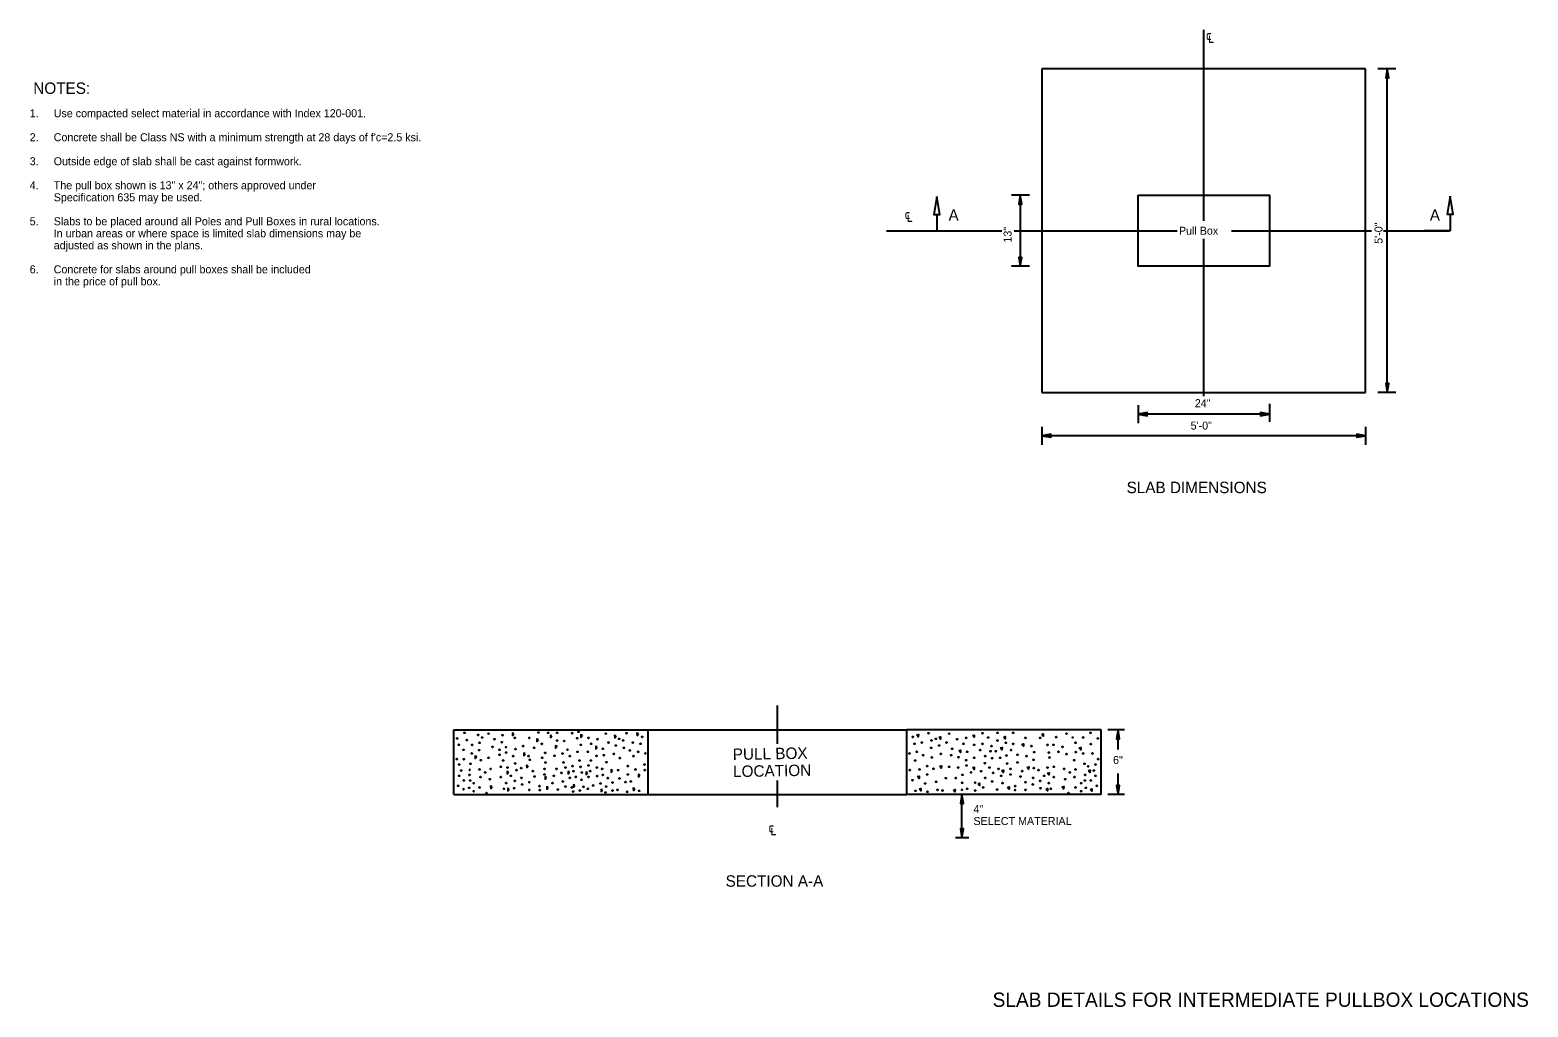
# Model space of a CAD drawing. Extents: x 10083 to 10738, y 10044 to 10472.
import ezdxf

# ---------------------------------------------------------------- set-up
doc = ezdxf.new("R2010")
doc.units = 0
doc.layers.add('Default', color=7, linetype='Continuous')
doc.layers.add('Dimension', color=7, linetype='Continuous')

msp = doc.modelspace()

# ---------------------------------------------------------------- linework, layer by layer
at = {"layer": 'Default'}
for p, q in [((10596.24, 10388), (10596.24, 10471.52)), ((10525.46, 10454.51), (10525.46, 10312.95)), ((10667.02, 10454.51), (10525.46, 10454.51)), ((10667.02, 10312.95), (10667.02, 10454.51)), ((10680.27, 10454.51), (10672.4, 10454.51)), ((10676.48, 10312.95), (10676.48, 10454.51)), ((10520.08, 10399.3), (10512.21, 10399.3)), ((10516, 10399.3), (10516, 10368.16)), ((10457.46, 10383.73), (10507.34, 10383.73)), ((10506.24, 10383.73), (10507.97, 10383.73)), ((10513.3, 10383.73), (10584.64, 10383.73)), ((10596.24, 10311.43), (10596.24, 10380.23)), ((10608.31, 10383.73), (10669.64, 10383.73)), ((10674.77, 10383.73), (10703.82, 10383.73)), ((10677.04, 10383.73), (10684.02, 10383.73)), ((10520.08, 10368.16), (10512.21, 10368.16)), ((10525.46, 10312.95), (10667.02, 10312.95)), ((10680.27, 10312.95), (10672.4, 10312.95)), ((10567.54, 10307.43), (10567.54, 10299.56)), ((10624.95, 10308), (10624.95, 10300.13)), ((10624.95, 10303.5), (10567.54, 10303.5)), ((10525.46, 10297.98), (10525.46, 10290.1)), ((10667.02, 10294.04), (10525.46, 10294.04)), ((10667.02, 10297.98), (10667.02, 10290.1)), ((10409.81, 10159.41), (10409.81, 10176.1)), ((10268.22, 10165.47), (10353.2, 10165.47)), ((10268.22, 10137.16), (10268.22, 10165.47)), ((10353.2, 10137.16), (10353.2, 10165.47)), ((10353.2, 10165.47), (10466.42, 10165.47)), ((10466.42, 10137.16), (10466.42, 10165.47)), ((10551.4, 10165.47), (10466.42, 10165.47)), ((10551.4, 10137.16), (10551.4, 10165.47)), ((10561.58, 10165.47), (10554.23, 10165.47)), ((10558.74, 10156.86), (10558.74, 10165.47)), ((10409.81, 10131.69), (10409.81, 10143.25)), ((10558.74, 10137.16), (10558.74, 10146.31)), ((10268.22, 10137.16), (10353.2, 10137.16)), ((10353.2, 10137.16), (10466.42, 10137.16)), ((10551.4, 10137.16), (10466.74, 10137.16)), ((10490.5, 10118.25), (10490.5, 10137.16)), ((10561.58, 10137.16), (10554.23, 10137.16)), ((10493.57, 10118.24), (10487.62, 10118.24))]:
    msp.add_line(p, q, dxfattribs=at)
msp.add_lwpolyline([(10567.54, 10399.3), (10624.95, 10399.3), (10624.95, 10368.16), (10567.54, 10368.16)], close=True, dxfattribs=at)
for points in [[(10294.57, 10163.83), (10293.91, 10164.03), (10293.97, 10163.02), (10294.57, 10163.83)], [(10305.25, 10161.21), (10304.59, 10161.42), (10304.64, 10160.41), (10305.25, 10161.21)], [(10311.16, 10162.84), (10310.5, 10163.04), (10310.56, 10162.04), (10311.16, 10162.84)], [(10324.5, 10163.07), (10323.84, 10163.28), (10323.89, 10162.27), (10324.5, 10163.07)], [(10339.27, 10162.83), (10338.61, 10163.03), (10338.66, 10162.02), (10339.27, 10162.83)], [(10349.03, 10163.85), (10348.37, 10164.05), (10348.42, 10163.04), (10349.03, 10163.85)], [(10470.77, 10163.28), (10471.43, 10163.48), (10471.37, 10162.47), (10470.77, 10163.28)], [(10480.47, 10162.25), (10481.13, 10162.46), (10481.08, 10161.45), (10480.47, 10162.25)], [(10495.2, 10162.99), (10495.86, 10163.19), (10495.8, 10162.19), (10495.2, 10162.99)], [(10508.79, 10162.32), (10509.45, 10162.53), (10509.39, 10161.52), (10508.79, 10162.32)], [(10525.4, 10163.47), (10526.06, 10163.67), (10526.01, 10162.66), (10525.4, 10163.47)], [(10299.55, 10155.04), (10298.89, 10155.25), (10298.95, 10154.24), (10299.55, 10155.04)], [(10313.41, 10158.2), (10312.75, 10158.41), (10312.81, 10157.4), (10313.41, 10158.2)], [(10331.03, 10158.01), (10330.37, 10158.21), (10330.43, 10157.21), (10331.03, 10158.01)], [(10489.24, 10156.37), (10489.9, 10156.57), (10489.84, 10155.57), (10489.24, 10156.37)], [(10507.35, 10157.58), (10508.01, 10157.78), (10507.95, 10156.78), (10507.35, 10157.58)], [(10516.75, 10159.1), (10517.41, 10159.3), (10517.36, 10158.3), (10516.75, 10159.1)], [(10541.82, 10157.52), (10542.48, 10157.72), (10542.42, 10156.72), (10541.82, 10157.52)], [(10275.47, 10148.04), (10275.14, 10148.15), (10275.17, 10147.64), (10275.47, 10148.04)], [(10278.29, 10153.68), (10277.63, 10153.88), (10277.68, 10152.88), (10278.29, 10153.68)], [(10300.78, 10149.73), (10300.12, 10149.93), (10300.18, 10148.92), (10300.78, 10149.73)], [(10337.68, 10147.82), (10337.02, 10148.02), (10337.08, 10147.01), (10337.68, 10147.82)], [(10480.85, 10149.54), (10481.51, 10149.74), (10481.45, 10148.74), (10480.85, 10149.54)], [(10495.23, 10148.94), (10495.89, 10149.14), (10495.84, 10148.14), (10495.23, 10148.94)], [(10519.04, 10149.02), (10519.7, 10149.22), (10519.65, 10148.22), (10519.04, 10149.02)], [(10292.19, 10146.97), (10291.54, 10147.18), (10291.59, 10146.17), (10292.19, 10146.97)], [(10308.87, 10144.72), (10308.21, 10144.92), (10308.27, 10143.91), (10308.87, 10144.72)], [(10318.92, 10147.05), (10318.26, 10147.25), (10318.31, 10146.24), (10318.92, 10147.05)], [(10321.23, 10141.25), (10320.58, 10141.45), (10320.63, 10140.45), (10321.23, 10141.25)], [(10326.8, 10146.74), (10326.14, 10146.94), (10326.19, 10145.93), (10326.8, 10146.74)], [(10349.68, 10145.68), (10349.02, 10145.88), (10349.08, 10144.87), (10349.68, 10145.68)], [(10471.11, 10145.03), (10471.77, 10145.24), (10471.71, 10144.23), (10471.11, 10145.03)], [(10497.57, 10141.87), (10498.23, 10142.08), (10498.18, 10141.07), (10497.57, 10141.87)], [(10507.97, 10147.64), (10508.63, 10147.84), (10508.58, 10146.84), (10507.97, 10147.64)], [(10527.93, 10146.52), (10528.59, 10146.72), (10528.53, 10145.72), (10527.93, 10146.52)], [(10545.85, 10147.67), (10546.51, 10147.88), (10546.46, 10146.87), (10545.85, 10147.67)], [(10272.75, 10139.59), (10272.42, 10139.69), (10272.45, 10139.19), (10272.75, 10139.59)], [(10285.03, 10140.66), (10284.37, 10140.86), (10284.43, 10139.86), (10285.03, 10140.66)], [(10292.53, 10139.62), (10291.87, 10139.82), (10291.93, 10138.81), (10292.53, 10139.62)], [(10309.55, 10140.33), (10308.89, 10140.54), (10308.95, 10139.53), (10309.55, 10140.33)], [(10333.32, 10139.24), (10332.66, 10139.44), (10332.71, 10138.44), (10333.32, 10139.24)], [(10347.4, 10139.71), (10346.74, 10139.91), (10346.8, 10138.9), (10347.4, 10139.71)], [(10471.88, 10139.62), (10472.54, 10139.83), (10472.48, 10138.82), (10471.88, 10139.62)], [(10486.8, 10139.12), (10487.46, 10139.32), (10487.41, 10138.32), (10486.8, 10139.12)], [(10510.48, 10140.3), (10511.14, 10140.5), (10511.08, 10139.49), (10510.48, 10140.3)], [(10527.28, 10139.58), (10527.94, 10139.78), (10527.88, 10138.77), (10527.28, 10139.58)], [(10534.34, 10140.48), (10535, 10140.68), (10534.94, 10139.67), (10534.34, 10140.48)], [(10546.68, 10139.41), (10547.34, 10139.61), (10547.29, 10138.61), (10546.68, 10139.41)]]:
    msp.add_lwpolyline(points, dxfattribs=at)
for centre in [(10269.74, 10161.72), (10272.94, 10164.16), (10273.97, 10160.98), (10278.95, 10163.22), (10280.71, 10162.11), (10283.46, 10163.79), (10286.09, 10161.34), (10289.52, 10163.1), (10294.92, 10161.91), (10301.3, 10161.91), (10305.34, 10164.31), (10309.57, 10164.15), (10313.51, 10164.16), (10320.09, 10163.98), (10322.16, 10161.77), (10322.79, 10164.63), (10327.23, 10161.91), (10331.17, 10161.34), (10334.74, 10163.79), (10340.57, 10161.53), (10342.37, 10160.86), (10343.76, 10163.98), (10350.61, 10162.36), (10469, 10162.36), (10475.85, 10163.98), (10477.24, 10160.86), (10479.05, 10161.53), (10484.87, 10163.79), (10488.44, 10161.34), (10492.39, 10161.91), (10499.52, 10163.98), (10501.96, 10162.11), (10506.1, 10164.16), (10512.86, 10164.16), (10518.31, 10161.91), (10524.7, 10161.91), (10531.65, 10162.28), (10536.16, 10163.79), (10538.91, 10162.11), (10543.48, 10162.14), (10546.68, 10164.16), (10549.87, 10161.72), (10270.42, 10158.94), (10272.47, 10156.72), (10276.13, 10155.14), (10276.35, 10158.84), (10279.42, 10156.58), (10279.51, 10159.84), (10285.15, 10157.96), (10288.23, 10156.76), (10288.26, 10154.6), (10289.31, 10160.01), (10291.1, 10157.9), (10291.16, 10155.52), (10295.21, 10157.03), (10298.67, 10158.34), (10303.45, 10157.65), (10306.75, 10159.28), (10308.24, 10155.38), (10313.51, 10160.78), (10315.77, 10155.07), (10316.55, 10160.58), (10318.04, 10156.79), (10322.31, 10155.85), (10323.85, 10158.9), (10326.85, 10155.89), (10328.39, 10159.36), (10333.43, 10157.21), (10333.88, 10154.36), (10335.88, 10159.86), (10338.31, 10154.95), (10339.13, 10158.61), (10342.63, 10157.58), (10345.25, 10156.45), (10346.62, 10159.86), (10348.83, 10155.89), (10349.86, 10159.36), (10352.03, 10155.14), (10467.59, 10155.14), (10469.75, 10159.36), (10470.78, 10155.89), (10473, 10159.86), (10473.49, 10154.36), (10476.98, 10157.58), (10480.49, 10158.61), (10481.3, 10154.95), (10483.73, 10159.86), (10485.73, 10154.36), (10486.19, 10157.21), (10491.22, 10159.36), (10492.76, 10155.89), (10495.77, 10158.9), (10498.46, 10156.61), (10499.52, 10159.28), (10502.96, 10156.11), (10503.45, 10158.36), (10505.35, 10156.08), (10506.1, 10160.78), (10509.67, 10159.84), (10511.94, 10156.61), (10512.86, 10159.28), (10514.77, 10154.6), (10520.94, 10158.34), (10522.07, 10155.7), (10527.92, 10158.86), (10528.46, 10155.52), (10530.52, 10158.9), (10532.78, 10155.89), (10534.47, 10157.96), (10536.16, 10154.86), (10540.1, 10159.84), (10540.34, 10155.72), (10543.48, 10155.14), (10546.8, 10159.23), (10547.64, 10155.18), (10269.55, 10152.7), (10270.68, 10150.25), (10272.72, 10152.61), (10275.56, 10150.63), (10279.51, 10148.18), (10280.07, 10152.13), (10283.45, 10153.26), (10284.39, 10148.37), (10288.9, 10149.31), (10289.87, 10152.09), (10291.72, 10148.94), (10294.19, 10154.01), (10295.05, 10150.76), (10295.69, 10147.87), (10297.73, 10148.75), (10300.93, 10154.01), (10301.55, 10152.4), (10306.88, 10153.26), (10307.88, 10148.37), (10308.37, 10151.15), (10312.28, 10154.13), (10313.14, 10148.37), (10316.26, 10151.23), (10317.08, 10148.94), (10318.96, 10154.01), (10320.16, 10149.61), (10323.18, 10152.01), (10323.62, 10149.22), (10327.14, 10149.86), (10328.19, 10152.01), (10330.62, 10154.05), (10330.8, 10148.94), (10333.13, 10148.36), (10335.09, 10151.3), (10340.19, 10147.81), (10340.89, 10153.11), (10344.37, 10149.61), (10346.89, 10153.98), (10347.71, 10148.18), (10351.69, 10150.26), (10351.86, 10147.87), (10467.75, 10147.87), (10470.02, 10152.01), (10471.91, 10148.18), (10475.24, 10149.61), (10477.27, 10153.39), (10478, 10148.44), (10484.83, 10149.27), (10488.82, 10148.94), (10489, 10153.45), (10492.35, 10152.17), (10492.47, 10149.86), (10495.8, 10153.26), (10500.5, 10150.83), (10500.65, 10154.01), (10502.53, 10148.94), (10503.64, 10153.03), (10506.47, 10148.37), (10507.23, 10153.26), (10510.04, 10154.2), (10510.3, 10150.68), (10511.74, 10148.37), (10514.77, 10151.23), (10518.69, 10154.01), (10521.72, 10152.4), (10521.88, 10148.75), (10523.93, 10147.87), (10527.89, 10148.94), (10528.71, 10153.34), (10530.71, 10149.31), (10535.22, 10148.37), (10539.54, 10152.13), (10540.1, 10148.18), (10544.05, 10150.63), (10545.74, 10149.5), (10548.93, 10150.25), (10550.06, 10152.7), (10270.68, 10145.36), (10271.43, 10147.62), (10272.72, 10143.37), (10275.19, 10145.74), (10275.38, 10143.3), (10276.96, 10142.12), (10279.89, 10144.8), (10281.95, 10146.87), (10284.02, 10143.86), (10288.9, 10144.8), (10291.16, 10142.17), (10293.22, 10145.36), (10294.94, 10143.12), (10297.92, 10144.42), (10298.11, 10141.6), (10301.3, 10142.54), (10302.81, 10147.43), (10303.56, 10144.99), (10307.88, 10145.93), (10311.45, 10142.17), (10312.01, 10145.36), (10315.41, 10146.62), (10315.96, 10142.92), (10318.96, 10144.42), (10320.65, 10147.37), (10321.7, 10144.89), (10324.17, 10143.66), (10324.32, 10146.79), (10327.14, 10144.89), (10327.84, 10147.44), (10331.02, 10145.27), (10332.42, 10142.06), (10333.48, 10145.74), (10335.63, 10144.37), (10337.63, 10142.37), (10340.75, 10144.24), (10343.37, 10142.62), (10344.32, 10145.93), (10345.64, 10142.92), (10468.92, 10143.39), (10474.35, 10141.99), (10475.29, 10145.93), (10479.19, 10142.76), (10483.42, 10144.33), (10487.86, 10144.36), (10490.55, 10142.34), (10490.77, 10145.79), (10494.45, 10146.87), (10496.33, 10142.36), (10498.96, 10147.37), (10500.65, 10144.42), (10503.66, 10142.92), (10504.2, 10146.62), (10507.6, 10145.36), (10508.17, 10142.17), (10511.74, 10145.93), (10516.06, 10144.99), (10516.81, 10147.43), (10518.31, 10142.54), (10521.5, 10141.6), (10521.69, 10144.42), (10524.68, 10143.12), (10526.39, 10145.36), (10528.46, 10142.17), (10530.71, 10144.8), (10535.59, 10143.86), (10537.66, 10146.87), (10539.73, 10144.8), (10542.65, 10142.12), (10544.24, 10143.3), (10544.42, 10145.74), (10546.9, 10143.37), (10548.18, 10147.62), (10548.93, 10145.36), (10270.12, 10141.04), (10275, 10140.1), (10276.96, 10138.62), (10279.51, 10140.29), (10282.52, 10137.84), (10290.22, 10139.72), (10294.73, 10139.91), (10301.3, 10139.16), (10305.81, 10140.85), (10305.92, 10139.12), (10313.7, 10139.35), (10317.17, 10140.65), (10319.9, 10140.29), (10320.46, 10138.46), (10323.4, 10138.87), (10325.03, 10140.59), (10326.85, 10139.72), (10329.27, 10141.15), (10334.65, 10138.02), (10334.85, 10140.65), (10337.63, 10138.87), (10339.82, 10139.16), (10344.14, 10138.41), (10349.4, 10138.78), (10470.22, 10138.78), (10475.48, 10138.41), (10479.8, 10139.16), (10481.98, 10138.87), (10490.51, 10139.21), (10492.76, 10139.72), (10496.21, 10138.87), (10499.71, 10140.29), (10505.91, 10139.35), (10513.69, 10139.12), (10513.8, 10140.85), (10518.31, 10139.16), (10524.89, 10139.91), (10529.39, 10139.72), (10537.1, 10137.84), (10540.1, 10140.29), (10542.65, 10138.62), (10544.61, 10140.1), (10549.5, 10141.04)]:
    msp.add_circle(centre, 0.202, dxfattribs=at)
at = {"layer": 'Dimension'}
for p, q in [((10479.57, 10390.96), (10479.57, 10383.73)), ((10704.04, 10390.95), (10704.05, 10383.73)), ((10479.57, 10383.73), (10490.99, 10383.73)), ((10704.05, 10383.73), (10692.62, 10383.73))]:
    msp.add_line(p, q, dxfattribs=at)
for points in [[(10676.48, 10454.51), (10675.82, 10450.61), (10677.14, 10450.61)], [(10479.57, 10398.67), (10478.25, 10390.86), (10480.89, 10390.86)], [(10516, 10399.3), (10515.34, 10395.4), (10516.67, 10395.4)], [(10704.04, 10398.77), (10702.72, 10390.95), (10705.37, 10390.96)], [(10516, 10368.16), (10516.67, 10372.07), (10515.34, 10372.07)], [(10676.48, 10312.95), (10677.14, 10316.86), (10675.82, 10316.86)], [(10567.54, 10303.5), (10571.44, 10302.83), (10571.44, 10304.16)], [(10624.95, 10303.5), (10621.04, 10304.16), (10621.04, 10302.83)], [(10525.46, 10294.04), (10529.37, 10293.38), (10529.37, 10294.7)], [(10667.02, 10294.04), (10663.12, 10294.7), (10663.12, 10293.38)], [(10558.74, 10165.47), (10558.08, 10161.57), (10559.41, 10161.57)], [(10490.5, 10137.16), (10489.84, 10133.26), (10491.16, 10133.26)], [(10558.74, 10137.16), (10559.41, 10141.07), (10558.08, 10141.07)], [(10490.5, 10118.25), (10491.16, 10122.15), (10489.84, 10122.15)]]:
    msp.add_lwpolyline(points, close=True, dxfattribs=at)

# ---------------------------------------------------------------- texts
at = {"layer": 'Default'}
for s, p in [('A', (10484.63, 10388.06)), ('A', (10695.09, 10388.06)), ('℄', (10405.81, 10119.87))]:
    msp.add_text(s, height=5, dxfattribs=at).set_placement(p)
at = {"layer": 'Dimension'}
for s, height, p in [('℄', 5, (10597.16, 10466.37)), ('NOTES:', 5, (10084.38, 10443.55)), ('1.', 3.5, (10082.81, 10433.35)), ('Use compacted select material in accordance with Index 120-001.', 3.5, (10093.31, 10433.35)), ('2.', 3.5, (10082.81, 10422.85)), ("Concrete shall be Class NS with a minimum strength at 28 days of f'c=2.5 ksi.", 3.5, (10093.31, 10422.85)), ('3.', 3.5, (10082.81, 10412.35)), ('Outside edge of slab shall be cast against formwork.', 3.5, (10093.31, 10412.35)), ('4.', 3.5, (10082.81, 10401.85)), ('The pull box shown is 13" x 24"; others approved under', 3.5, (10093.31, 10401.85)), ('Specification 635 may be used.', 3.5, (10093.31, 10396.6)), ('℄', 5, (10465.39, 10388.06)), ('5.', 3.5, (10082.81, 10386.1)), ('Slabs to be placed around all Poles and Pull Boxes in rural locations.', 3.5, (10093.31, 10386.1)), ('In urban areas or where space is limited slab dimensions may be', 3.5, (10093.31, 10380.85)), ('Pull Box', 3.5, (10585.39, 10381.98)), ('adjusted as shown in the plans.', 3.5, (10093.31, 10375.6)), ('6.', 3.5, (10082.81, 10365.1)), ('Concrete for slabs around pull boxes shall be included', 3.5, (10093.31, 10365.1)), ('in the price of pull box.', 3.5, (10093.31, 10359.85)), ('24"', 3.5, (10592.32, 10306.56)), ('5\'-0"', 3.5, (10590.5, 10296.76)), ('SLAB DIMENSIONS', 5, (10562.49, 10268.96)), ('6"', 3.5, (10556.57, 10150.5)), ('4"', 3.5, (10495.52, 10129.09)), ('SELECT MATERIAL', 3.5, (10495.52, 10123.84)), ('SECTION A-A', 5, (10387.14, 10096.86)), ('SLAB DETAILS FOR INTERMEDIATE PULLBOX LOCATIONS', 6.25, (10503.9, 10044.33))]:
    msp.add_text(s, height=height, dxfattribs=at).set_placement(p)
for s, height, rotation, p in [('13" ', 3.5, 90, (10512.19, 10378.53)), ('5\'-0"', 3.5, 90, (10674.41, 10377.99)), ('PULL BOX', 5, 1, (10390.31, 10152.27)), ('LOCATION', 5, 1, (10390.44, 10144.77))]:
    msp.add_text(s, height=height, rotation=rotation, dxfattribs=at).set_placement(p)

doc.saveas('drawing.dxf')
